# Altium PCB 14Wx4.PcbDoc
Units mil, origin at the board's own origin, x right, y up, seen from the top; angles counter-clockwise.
Board outline 11600 x 1085 mil, 2 copper layers (Top Layer, Bottom Layer); 105 components, 57 nets, 293 pads, 0 vias.
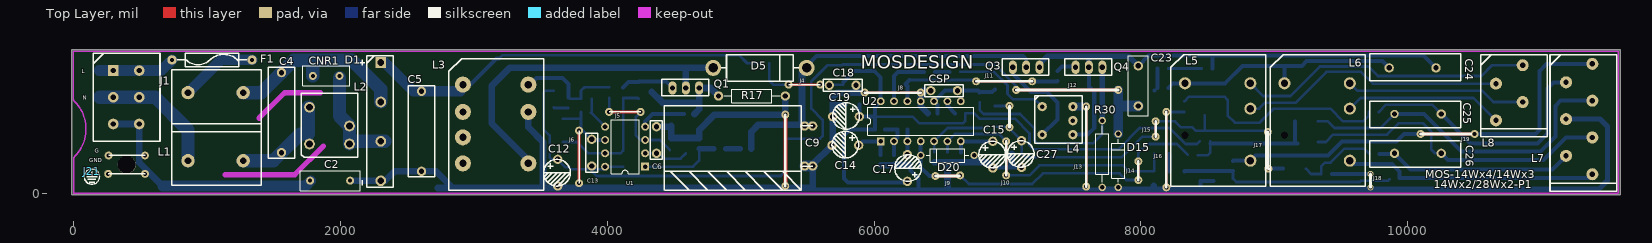
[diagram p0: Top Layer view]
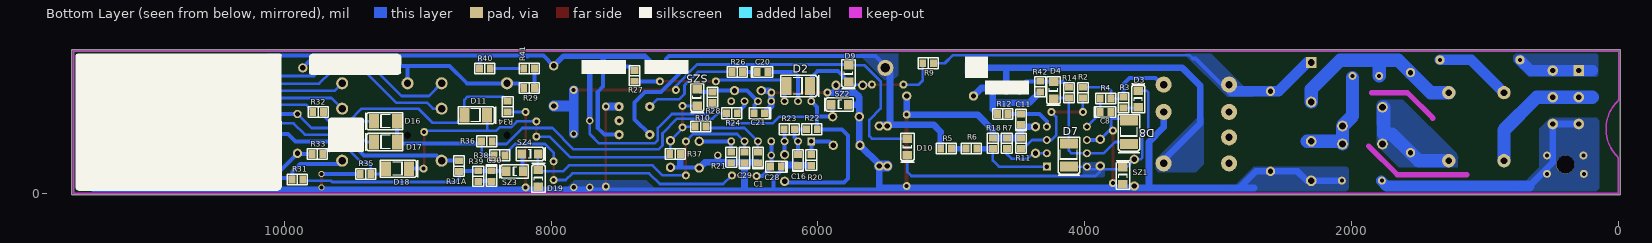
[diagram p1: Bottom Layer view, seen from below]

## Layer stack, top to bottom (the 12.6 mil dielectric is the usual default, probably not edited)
Top Layer: signal copper 1.4
Dielectric: dielectric 12.6, FR-4, Dk 4.8
Bottom Layer: signal copper 1.4

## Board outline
-10,-10 11590,-10 11590,1075 -10,1075

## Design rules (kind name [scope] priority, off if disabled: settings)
Clearance [All] p1: gap=10
HoleSize [All] p1: absolutevalues=TRUE maxlimit=150 minlimit=1 maxpercent=80.000 minpercent=20.000
PlaneClearance [All] p1: clearance=10
PolygonConnect [All] p1: connectstyle=Direct reliefconductorwidth=10 reliefentries=4 polygonreliefangle="90 Angle"
RoutingVias [All] p1: holewidth=28 width=50 viastyle="Through Hole" minholewidth=28 minwidth=50 maxholewidth=28 maxwidth=50
SolderMaskExpansion [All] p1: expansion=4
TestPointUsage [All] p1: valid=0 allowmultiple=FALSE
Testpoint [All] p1: side=15 testpointundercomponent=TRUE minsize=40 maxsize=100 preferedsize=60 minholesize=0 maxholesize=40 preferedholesize=32 testpointgrid=1 style=1023 order=0-112345678
Width [All] p1: maxlimit=100 minlimit=10 preferedwidth=10 toplayer_minwidth=20 toplayer_maxwidth=20 toplayer_prefwidth=20 bottomlayer_prefwidth=20 minimp=50.000000 maximp=50.000000 favimp=50.000000
17 further rules are at their usual default settings.

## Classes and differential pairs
component class 20081009SMD: C2 C4 C5 C6 C8 C9 C11 C12 C13 C14 C15 C16 C17 C18 C19 C20 C21 C23 C24 C25 C26 C27 C28 C29 C30 CNR1 D1 D3 D4 D5 D9 D10 D11 D15 D16 D17 D18 D19 D20 F1 J1 L1 L2 L3 L4 L5 L6 L7 Q1 Q3 Q4 R2 R3 R4 R5 R6 R7 R9 R10 R11 R12 R14 R17 R18 R20 R21 R22 R23 R24 R26 R27 R28 R29 R30 R31 R31A R32 R33 R34 R35 R36 R37 R38 R39 R40 R41 R42 SZ1 SZ2 SZ3 SZ4 U1 U2
net class NewClass: E

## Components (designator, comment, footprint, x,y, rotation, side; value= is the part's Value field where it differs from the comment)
C1 "Comment" C0805A 6450,270 r90 bottom
C2 "Cap Y1" RAD-0.3#1 1925,95 r180 top
C4 "Cap X1" RAD0.6B 1560,305 r90 top
C5 "CAP" RAD0.6B 2610,165 r90 top
C6 "CAP" RAD0.2B 4370,500 r270 top
C8 "CAP" C0805A 3845,610 r180 bottom
C9 "Cap2" RB.3/.6A 5540,505 r0 top locked
C11 "CAP" C0805A 4480,555 r90 bottom
C12 "CAP" RB.2/.2 3630,155 r0 top
C13 "Comment" RAD0.2B 3885,205 r90 top
C14 "Cap" RB.2/.2 5785,360 r270 top
C15 "Cap" RB.2/.2 6890,290 r0 top
C16 "Cap" C0805A 6150,250 r90 bottom
C17 "Cap2" RB.2/.2 6250,190 r180 top
C18 "CAP" RAD0.2B 5865,810 r180 top
C19 "Cap" RB.2/.2 5790,575 r270 top
C20 "CAP" C0805A 6415,910 r180 bottom
C21 "CAP" C0805A 6440,600 r0 bottom
C23 "CAP" RAD-0.3#2 7980,805 r270 top
C24 "CAP" RAD0.6A#1 9710,840 r0 top
C25 "CAP" RAD0.6A#2 10400,695 r180 top
C26 "CAP" RAD0.6A#1 10400,400 r180 top
C27 "Cap2" RB.2/.2 7105,295 r0 top
C28 "Cap" C0805A 6315,200 r0 bottom
C29 "Cap" C0805A 6550,270 r90 bottom
C30 "Cap" C0805A 8445,130 r270 bottom
CNR1 "CNR" RAD-0.2 1895,880 r0 top
CSP "Comment" RAD0.2B 6425,770 r0 top
D1 "DIODEx4" SIP4B 2305,980 r270 top
D2 "Comment" CD4532-1812A 6140,805 r180 bottom
D3 "DIODE" CD3216-1206A 3600,705 r90 bottom
D4 "DIODE" CD3216-1206A 4235,775 r270 bottom
D5 "HIGH EFFICIENCY DIODES" DIODE0.7A 4850,835 r0 top
D7 "Comment" CD4532-1812A 4120,280 r270 bottom
D8 "Comment" CD4532-1812A 3670,450 r270 bottom
D9 "DIODE" CD3216-1206A 5770,900 r270 bottom
D10 "DIODE" CD3216-1206A 5330,350 r270 bottom
D11 "DIODE" CD4532-1810 8555,585 r180 bottom
D15 "FFAST RECOVERY RECTIFIER" DIODE-0.4 7830,245 r90 top
D16 "Surface Mount Glass Passivated Rectifier" CD4532-1810 9250,540 r0 bottom
D17 "Surface Mount Glass Passivated Rectifier" CD4532-1810 9250,385 r0 bottom
D18 "DIODE" CD4532-1810 9140,185 r180 bottom
D19 "DIODE" CD3216-1206A 8095,110 r90 bottom
D20 "HIGH EFFICIENCY DIODES" DIODE-0.4 6550,285 r180 top
F1 "3.15A/250V" FUSE0.6 740,1000 r0 top
GND "Comment" GND 400,215 r0 top
J1 "Header 3" IDC6C 300,920 r0 top
J4 "Comment" JUMP_6mm 5360,815 r0 top
J5 "Comment" JUMP_6mm 4015,610 r0 top
J6 "Comment" JUMP_10mm 3790,470 r270 top
J21 "Comment" GND2 140,165 r0 top
L1 "INDUCTOR_EMI" EE1916H_EMI 740,60 r0 top
L2 "Inductor" Q.3/.3 1770,370 r0 top
L3 "INDUCTOR2:2_3" EE25_PFC8 3165,520 r270 top locked
L4 "INDUCTOR2:2" EE0808 7490,545 r270 top
L5 "INDUCTOR2A" EE2520_LRES8 8330,825 r0 top locked
L6 "INDUCTOR" EE2520_LRES8 9075,825 r0 top
L7 "Comment" IDC14-MIN 11065,1040 r270 top
L8 "Comment" IDC8-MIN 10660,960 r270 top
Q1 "MOSFET-N" TO-220D 4590,790 r0 top
Q3 "MOSFET-N" TO-220D 7140,945 r0 top
Q4 "MOSFET-N" TO-220D 7610,945 r0 top
R2 "RES1" 2012[0805]A 4015,755 r270 bottom
R3 "RES1" 2012[0805]A 3710,680 r270 bottom
R4 "RES1" 2012[0805]A 3845,710 r0 bottom
R5 "RES1" 2012[0805]A 5040,335 r0 bottom
R6 "RES1" 2012[0805]A 4850,335 r180 bottom
R7 "Res1" 2012[0805]A 4585,375 r270 bottom
R9 "RES1" 2012[0805]A 5175,975 r180 bottom
R10 "RES1" 2012[0805]A 6880,500 r180 bottom
R11 "RES1" 2012[0805]A 4480,375 r90 bottom
R12 "RES1" 2012[0805]A 4615,595 r0 bottom
R14 "RES1" 2012[0805]A 4120,755 r90 bottom
R17 "RES1" AXIAL-0.5#1 5085,730 r180 top
R18 "RES1" 2012[0805]A 4690,375 r270 bottom
R20 "RES1" 2012[0805]A 6050,250 r90 bottom
R21 "RES1" 2012[0805]A 6650,270 r90 bottom
R22 "RES1" 2012[0805]A 6045,480 r180 bottom
R23 "RES1" 2012[0805]A 6215,480 r0 bottom
R24 "RES1" 2012[0805]A 6645,600 r0 bottom
R26 "RES1" 2012[0805]A 6605,910 r180 bottom
R27 "RES1" 2012[0805]A 7375,880 r90 bottom
R28 "RES1" 2012[0805]A 6790,720 r90 bottom
R29 "Res1" 2012[0805]A 8165,790 r180 bottom
R30 "RES1" AXIAL-0.5#2 7710,295 r90 top
R31 "RES1" 2012[0805]A 9900,105 r0 bottom
R31A "RES1" 2012[0805]A 8690,205 r90 bottom (schematic designator R31)
R32 "RES1" 2012[0805]A 9745,610 r180 bottom
R33 "RES1" 2012[0805]A 9750,295 r180 bottom
R34 "RES1" 2012[0805]A 8325,650 r90 bottom
R35 "RES1" 2012[0805]A 9390,145 r180 bottom
R36 "RES1" 2012[0805]A 8480,390 r180 bottom
R37 "RES1" 2012[0805]A 7070,295 r0 bottom
R38 "RES1" 2012[0805]A 8385,285 r180 bottom
R39 "RES1" 2012[0805]A 8545,130 r90 bottom
R40 "Res1" 2012[0805]A 8495,935 r180 bottom
R41 "Res1" 2012[0805]A 8165,935 r0 bottom
R42 "RES1" 2012[0805]A 4335,800 r270 bottom
SZ1 "Zener" CD3216-1206A 3715,130 r90 bottom
SZ2 "Zener" CD3216-1206A 5835,665 r0 bottom
SZ3 "Zener" CD3216-1206A 8270,165 r0 bottom
SZ4 "Zener" CD3216-1206A 8160,295 r180 bottom
SZ5 "Comment" CD3216-1206A 6905,720 r270 bottom
U1 "IC" DIP-8 4135,350 r90 top
U2 "IC" DIP-14 6350,540 r0 top

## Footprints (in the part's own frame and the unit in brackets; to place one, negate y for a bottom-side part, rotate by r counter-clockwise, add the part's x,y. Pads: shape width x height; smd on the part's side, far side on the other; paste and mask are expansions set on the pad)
2012[0805]A [mm] "Chip Resistor; Body 2.0 x 1.3 mm (LxW typ)"
  rect 1.3x1.5 smd: 1(-1.016,0) 2(1.016,0)
  silkscreen extent -1.91,-1.02 1.91,1.02
AXIAL-0.5#1 [mil] "Semiconductor Resistor; 2 Leads"
  round 70 hole 40: 1(-250,0) 2(250,0)
  silkscreen extent -210,-50 210,50
AXIAL-0.5#2 [mil] "Semiconductor Resistor; 2 Leads"
  round 55.12 hole 33.46: 1(-250,0) 2(250,0)
  silkscreen extent -210,-50 210,50
C0805A [mm] "Chip Capacitor; Body 2.0 x 1.2 mm (LxW typ)"
  rect 1.3x1.5 smd: 1(-1.016,0) 2(1.016,0)
  silkscreen extent -2.16,-1.02 1.91,1.02
CD3216-1206A [mm] "Chip Diode; Body 3.2 x 1.6 mm (LxW typ)"
  rect 1.6x1.8 smd: 1(-1.524,0) 2(1.651,0)
  silkscreen extent -2.54,-1.27 2.92,1.27
CD4532-1810 [mm] "Chip Diode; Body 4.5 x 3.2 mm (LxW typ)"
  rect 1.9x2.8 smd: 1(-2.413,0) 2(1.95,0)
  silkscreen extent -3.56,-1.65 3.56,1.65
CD4532-1812A [mm] "Chip Diode; Body 4.5 x 3.2 mm (LxW typ)"
  rect 1.9x3.4 smd: 1(-2.413,0) 2(2.032,0)
  silkscreen extent -3.56,-2.03 3.68,2.03
DIODE0.7A [mil]
  round 120 hole 70: 1(-55,105) 2(645,105)
  silkscreen extent 5,5 585,205
DIODE-0.4 [mm] "Tunnel Diode - Dependent Source Model; 2 Leads"
  round 1.4 hole 0.85: 1(-5.08,0) 2(5.08,0)
  silkscreen extent -4.06,-1.27 4.06,1.27
DIP-8 [mm] "DIP; 8 Leads; Row Spacing 7.62 mm; Pitch 2.54 mm"
  rect 1.5x1.5 hole 0.9: 1(-3.81,-3.81)
  round 1.5 hole 0.9: 2(-1.27,-3.81) 3(1.27,-3.81) 4(3.81,-3.81) 5(3.81,3.81) 6(1.27,3.81) 7(-1.27,3.81) 8(-3.81,3.81)
  silkscreen extent -5.15,-2.65 5.15,2.65
DIP-14 [mm] "DIP; 14 Leads; Row Spacing 7.62 mm; Pitch 2.54 mm"
  rect 1.5x1.5 hole 0.9: 1(-7.62,-3.81)
  round 1.5 hole 0.9: 2(-5.08,-3.81) 3(-2.54,-3.81) 4(0,-3.81) 5(2.54,-3.81) 6(5.08,-3.81) 7(7.62,-3.81) 8(7.62,3.81) 9(5.08,3.81) 10(2.54,3.81) 11(0,3.81) 12(-2.54,3.81) 13(-5.08,3.81) 14(-7.62,3.81)
  silkscreen extent -10.1,-2.65 10.1,2.65
EE25_PFC8 [mil]
  round 120 hole 55: 1(-295,-245) 2(-90,-245) 3(100,-245) 4(295,-245) 5(295,245) 7(-90,245) 8(-295,245)
  silkscreen extent -490,-350 495,360
EE0808 [mil]
  round 70 hole 35: 1(-105,-230) 3(105,-230) 4(105,0) 5(0,0)
  round 70 hole 32: 6(-105,0)
  silkscreen extent -185,-285 170,70
EE1916H_EMI [mil]
  round 100 hole 50: 1(120,185) 2(533.5,185) 3(533.5,695) 4(120,695)
  silkscreen extent 0,0 669,866
EE2520_LRES8 [mil]
  round 0 hole 55: 0(0,-390)
  round 90.55 hole 55: 1(0,0) 5(490,-580) 7(490,-190) 8(490,0)
  silkscreen extent -105,-770 605,215
FUSE0.6 [mil]
  round 70 hole 32: 1(0,0) 2(600,0)
  silkscreen extent 40,-50 560,50
GND [mil] "GND"
  round 60 hole 30: ""(-137.8,-68.9) ""(-135,68.9) ""(137.8,-68.9) ""(137.8,68.9)
  round 135 hole 135: ""(0,0)
  silkscreen extent -138,-69 138,69
GND2 [mil]
  silkscreen extent -57,-97 57,17
IDC6C [mil]
  rect 80x80 hole 40: 1(0,0)
  round 80 hole 40: 1(195,0) 2(0,-200) 2(195,-200) 3(0,-400) 3(195,-400)
  silkscreen extent -150,-530 350,130
IDC8-MIN [mil]
  round 90 hole 40: 1(0,200) 2(137.8,0) 3(275.59,200) 4(413.39,0)
  silkscreen extent -80,-115 535,385
IDC14-MIN [mil]
  round 90 hole 40: 1(70,316.85) 2(207.8,120) 3(345.59,316.85) 4(483.39,120) 5(621.18,316.85) 6(758.98,120) 7(896.77,316.85)
  silkscreen extent 0,0 1024,500
JUMP_6mm [mil]
  round 60 hole 30: 1(0,0) 2(236.22,0)
  silkscreen extent 0,0 236,0
JUMP_10mm [mil]
  round 60 hole 30: 1(0,0) 2(393.7,0)
  silkscreen extent 0,0 394,0
Q.3/.3 [mil]
  round 80 hole 50: 1(0,0) 1(0,275) 2(300,0) 2(300,135)
  silkscreen extent -60,-100 360,380
RAD0.2B [mil]
  round 70 hole 40: 1(0,0) 2(200,0)
  silkscreen extent -45,-45 245,45
RAD0.6A#1 [mil]
  round 70 hole 40: 1(150,100) 2(500,100)
  silkscreen extent 5,5 685,205
RAD0.6A#2 [mil]
  round 70 hole 40: 1(150,100)
  round 62.99 hole 40: 2(500,100)
  silkscreen extent 5,5 685,205
RAD0.6B [mil]
  round 70 hole 40: 1(0,0) 2(600,0)
  silkscreen extent -40,-100 640,100
RAD-0.2 [mil] "Jumper Wire; 2 Leads"
  round 60 hole 30: 1(-100,0) 2(100,0)
  silkscreen extent -175,-75 175,75
RAD-0.3#1 [mil] "Capacitor; 2 Leads"
  round 60 hole 30: 1(-150,0) 2(150,0)
  silkscreen extent -225,-75 225,75
RAD-0.3#2 [mil] "Capacitor; 2 Leads"
  round 70 hole 40: 1(-150,0) 2(150,0)
  silkscreen extent -225,-75 225,75
RB.2/.2 [mil]
  round 70 hole 40: 1(0,100) 2(0,-100)
  silkscreen extent -105,-100 95,100
RB.3/.6A [mil]
  round 70 hole 40: 1(0,0) 2(0,-300)
  silkscreen extent -1110,-480 0,150
SIP4B [mil]
  rect 80x80 hole 50: 1(0,0)
  round 80 hole 50: 2(295.28,0) 3(590.55,0) 4(885.83,0)
  silkscreen extent -50,-160 935,92
TO-220D [mil]
  oval 60x100 hole 40: 1(0,0) 2(-100,0) 3(100,0)
  silkscreen extent -180,-60 170,65

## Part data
C2: library part CAP, "Y Capacitor"
C4: library part CAP, "BOX Capacitor"
C5 C23 C24 C25 C26: "POLYPROPYLENE FILM Capacitor"
C6 C8 C11 C16 C18 C20 C21 C28 C29 C30: "Ceramic Capacitor"
C9 C17 C27: "Electrolytic Capacitor"
C12 C14 C15 C19: library part Cap2, "Electrolytic Capacitor"
CNR1: "Varistor"
D3 D4 D9 D10 D11 D18 D19: "Diode  75V,1A"
D5: library part DIODE, "Diode HIGH EFFICIENCY RECTIFIERS 600V, 3A"
D15 D16 D17: library part DIODE, "Diode FAST RECOVERY RECTIFIER 700V,1A"
D20: library part DIODE, "Diode HIGH EFFICIENCY RECTIFIERS 600V, 1A"
F1: library part FUSE2, "Fuse"
J1: "Jumper Wire Pin spacing 5mm         235-403(2LG+1G)"
L1: "EE19 Inductor"
L2: "DR1012 Inductor"
L3 L5: "EE25 Inductor"
L4: "EE08 Inductor"
L6: library part INDUCTOR2A, "EE25 Inductor"
Q1: "Transistor, MOSFET  600V, 11A"
Q3 Q4: "Transistor, MOSFET  600V, 6A"
R2 R3 R4 R5 R6 R9 R10 R11 R12 R14 R18 R20 R21 R22 R23 R24 R26 R27 R28 R29 R31 R31A R32 R33 R34 R35 R36 R37 R38 R39 R40 R41 R42: "Resistor 1/4W"
R7: "Resistor"
R17 R30: "Resistor 1W"
SZ1 SZ2: library part "D Zener", "Zener Diode 1W"
SZ3 SZ4: library part "D Zener", "Zener Diode 1/4W"
U1: library part 59039, "IC, Power Factor Controller"
U2: library part M8145, "IC, Ballast Driver"

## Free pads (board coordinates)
  round 60 hole 30: 0(5335,590) 0(6645,135) 0(7015,655) 0(7065,775) 0(7185,840) 0(7980,100) 1(5335,55) 1(6765,840) 1(6990,390) 1(7015,495) 1(7980,240) 2(6990,135) 3(7590,650) 4(7590,50) 5(6350,755) 5(7830,775) 6(5930,755) 7(6460,130) 8(8955,185) 8(10095,445) 9(8950,460) 9(10500,445) 17(8110,540) 18(8110,425) 19(8190,45) 20(8190,610)
  round 70 hole 40: 0(5480,505) 2(5480,205)
  round 45 hole 30: 11(9720,145) 12(9720,45)

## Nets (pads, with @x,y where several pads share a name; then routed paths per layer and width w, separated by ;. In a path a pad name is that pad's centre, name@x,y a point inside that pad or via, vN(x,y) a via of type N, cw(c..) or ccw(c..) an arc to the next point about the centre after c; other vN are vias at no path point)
E: C1.1 C2.1 C5.1 C6.1 C8.2 C9.2 C11.1 C12.2 C13.2 C14.2 C15.2 C16.1 C18.1 C19.2 C21.1 C27.2 C28.1 C29.1 C30.2 CSP.1 D1.4 D8.1 D15.1 D19.1 D20.1 J6.1 J6.2 L3.7 L4.6 L7.4 pad.0@5335,590 pad.1@5335,55 pad.2@5480,205 pad.3 pad.4 pad.5@6350,755 pad.6 pad.11 pad.12 pad.19 pad.20 R7.1 R11.2 R17.1 R18.1 R20.1 R21.1 R30.1 R34.1 R35.1 R37.1 R39.1 SZ1.1 SZ2.1 U1.6 U2.11 | length 19133.5
  Top Layer w20: J6.2 J6.1 ; pad.6 pad.5@6350,755 ; pad.4 pad.3 ; pad.19 pad.20 ; pad.12 pad.11
  Top Layer w30: pad.1@5335,55 pad.0@5335,590
  Bottom Layer w20: D8.1@3670,560 3805,560 ; 3790,40 J6.2 ; J6.1 J6.1@3800,480 ; C8.2 3805,560 ; C13.2 3810,480 J6.1@3800,480 ; C11.1@4475,500 4480,505 C11.1 C11.1@4480,520 ; pad.20 R34.1 ; 8455,25 8455,30 ; J6.1@3800,480 3805,485 3805,560
  Bottom Layer w30: C13.2 3890,400 U1.6 ; 5525,55 5540,40 5550,30 6335,30 ; C28.1@6262.4,212.6 C28.1 6275,170 6335,110 6335,30 ; U2.11@6347.6,692.4 U2.11 ; pad.5@6350,755 pad.5@6365,770 ; C29.1 C29.1@6550,232.6 ; C15.2 C15.2@6897.6,197.6 ; C15.2@6897.6,195 C27.2 ; 7032.6,207.4 7035,205 ; R30.1@7710,30 6335,30 ; 8455,30 8445,30 C30.2 8445,92.6 R39.1@8545,92.6 ; R35.1 9550,145 ; 9500,145 9550,145 ; pad.11 9550,145
  Bottom Layer w40: R30.1@7710,30 11430,30 11495,95 11495,500 11438.39,556.61 L7.4
  Bottom Layer w50: C2.1 2335.83,95 2405.83,165 C5.1 2720,165 2840,45 ; 2730,40 3790,40 5540,40 C9.2 5540,215 C14.2 ; L3.7 3410,495 3520,385 3520,50 ; C6.1 C11.1@4475,500 ; C11.1@4480,505 R11.2 R7.1 R18.1 4690,475 4805,590 5335,590 R17.1 ; C14.2@5690,360 C19.2 5690,666 ; SZ2.1 5691,665 5690,666 ; C18.1 5865,755 ; pad.6 5865,755 ; R20.1 6147.4,210 6150,212.6 C28.1@6262.4,212.6 ; pad.5@6350,755 U2.11 6350,652.6 C21.1@6402.6,600 ; pad.5@6365,770 CSP.1 ; C1.1@6450,232.6 6550,232.6 6750,232.6 ; 6550,45 C29.1 ; D20.1 6750,232.6 ; C15.2 6847.4,232.6 6750,232.6 ; 7032.6,207.4 R37.1@7032.6,295 ; D19.1@8095,54.88 8095,45 D19.1@8100,40 ; 5690,666 5690,721 5724,755 5865,755
  Bottom Layer w60: L4.6 pad.3
  Bottom Layer w80: pad.2@5480,205 C9.2
L: F1.1 J1.1 | length 578.1
  Bottom Layer w80: 195,920 495,920 660,920 F1.1
N: J1.2 L1.1 | length 1101.5
  Bottom Layer w100: 200,720 300,720 495,720 615,720 860,475 L1.1 860,355
NetC2_2: C2.2 GND. J1.3 | length 1859.1
  Bottom Layer w50: J1.3@300,520 495,520 495,230 670,55
  Bottom Layer w80: 670,55 1740,55 C2.2@1780,95
NetC4_1: C4.1 L1.2 L2.1 | length 769.3
  Bottom Layer w100: L1.2 1500,245 C4.1 1700,445 1760,445 L2.1@1760,645
NetC5_2: C5.2 D1.1 L3.1 R9.2 | length 2930
  Bottom Layer w20: 3190,1010 3215,1035 4990,1035 5050,975 R9.2
  Bottom Layer w30: L3.1@2975,815 3170,1010 3190,1010
  Bottom Layer w80: D1.1@2335,980 2550,765 L3.1@2900,765
NetC6_2: 
NetC8_1: C8.1 R4.2 | length 100
  Bottom Layer w20: C8.1 R4.2
NetC9_1: C9.1 D5.2 pad.0@5480,505 Q3.1 R5.2 | length 2843.2
  Bottom Layer w30: D5.2 5520,965 5520,980 5570,1030 7115,1030 7140,1005 Q3.1@7140,950
  Bottom Layer w50: R5.2 5080,460 5135,515 pad.0@5460,515 ; D5.2@5520,965 5460,905 pad.0@5460,515 ; C9.1 5530,515 pad.0@5460,515
NetC11_2: C11.2 R12.1 U1.4 | length 352.8
  Bottom Layer w30: U1.4 4285,540 4340,595 C11.2 R12.1
NetC12_1: C12.1 C13.1 D3.2 D7.2 D10.2 SZ1.2 U1.8 | length 2744.1
  Bottom Layer w20: D3.2 3540,770 3525,755 3525,480 3570,435 3570,270 3585,255 C12.1 SZ1.2@3690,195 ; SZ1.2@3730,180 C13.1@3890,180 ; D7.2 U1.8 3965,180 C13.1@3890,180 ; D10.2 5330,160 5300,130 3920,130 3890,160 C13.1@3890,180
NetC14_1: C14.1 R20.2 U2.1 | length 280
  Bottom Layer w30: C14.1 5915,390 U2.1 R20.2@6050,287.4
NetC15_1: C15.1 R21.2 U2.7 | length 322.6
  Bottom Layer w30: R21.2@6650,307.4 U2.7 C15.1
NetC16_2: C16.2 R22.1 R23.1 U2.2 | length 299.2
  Bottom Layer w30: R22.1@6082.4,480 6177.6,480 6177.6,417.6 U2.2 C16.2@6150,287.4
NetC17_2: C17.2 R23.2 U2.3 | length 191
  Bottom Layer w30: C17.2 U2.3 6250,477.6 R23.2@6252.4,480
NetC20_1: C20.1 R26.2 | length 110
  Bottom Layer w30: C20.1 R26.2
NetC20_2: C20.2 U2.13 | length 427.4
  Bottom Layer w30: U2.13 6150,880 6180,910 C20.2
NetC21_2: C21.2 CSP.2 R28.2 SZ5.1 U2.10 | length 603
  Bottom Layer w30: C21.2@6477.4,600 6477.4,662.6 U2.10 6530,770 CSP.2 6777.4,770 R28.2@6790,757.4 ; R28.2 6885,760 SZ5.1
NetC23_1: C23.1 C24.2 L4.4 Q3.3 Q4.1 R40.1 | length 4072.6
  Bottom Layer w30: L4.4 7600,440 7650,490 7650,760 7610,800 Q4.1@7610,940 ; C23.1 8057.24,1032.24 8185,1032.24 ; 8147.24,1032.24 8185,1032.24 ; 8177.4,1024.65 8185,1032.24 ; R40.1 8535,1025 ; C24.2 10117.76,1032.24 8270,1032.24 ; 8185,1032.24 8270,1032.24 ; 8185,1032.24 8270,1032.24
  Bottom Layer w40: Q3.3@7240,950 7240,968.99 7299,1027.99 7610,1027.99 ; Q4.1@7610,940 7610,1027.99 ; C23.1 7907.01,1027.99 7610,1027.99
NetC23_2: C23.2 D9.1 D10.1 D15.2 pad.0@7065,775 pad.5@7830,775 | length 3649.5
  Top Layer w20: pad.0@7065,775 pad.5@7830,775
  Bottom Layer w20: D10.1 5595,410 5615,430 5615,550 5530,635 5530,840 5650,960 D9.1@5759.88,960 ; D9.1@5764.88,965 6905,965 7065,805 pad.0@7065,775
  Bottom Layer w70: D15.2 pad.5@7830,775
  Bottom Layer w80: 7840,655 C23.2
NetC25_1: C25.2 D16.2 L7.3 | length 2527.1
  Bottom Layer w20: D16.2 9400,540 9450,490 9795,490 C25.2
  Bottom Layer w30: C25.2 10120,595 10400,315 10995,315 11105,425 11105,655 11144.41,694.41 L7.3
NetC25_2: C25.1 L7.2 R32.1 | length 1931.1
  Bottom Layer w20: R32.1@9782.4,610 9837.4,665 10180,665 C25.1
  Bottom Layer w30: C25.1 10470,375 10970,375 11045,450 11045,785 11092.2,832.2 L7.2
NetC26_1: C26.1 D17.2 L7.5 | length 2390.1
  Bottom Layer w20: D17.2 9385,385 9440,440 9845,440 9930,525 10115,525 10175,465 10175,330 10205,300 C26.1
  Bottom Layer w30: C26.1@10245,300 C26.1@10255,290 ; C26.1 10300,250 11016.18,250 11185,418.82 L7.5
NetC26_2: C26.2 L7.6 R33.1 | length 1491.2
  Bottom Layer w30: R33.1@9787.4,295 9895,295 C26.2 10020,180 11083.98,180 L7.6
NetC27_1: C27.1 D11.2 D18.2 pad.0@7015,655 pad.1@7015,495 pad.8@8955,185 pad.9@8950,460 pad.17 pad.18 R10.1 R37.2 SZ5.2 | length 3182.1
  Top Layer w20: pad.1@7015,495 pad.0@7015,655 ; pad.18 pad.17 ; pad.9@8950,460 8950,190 pad.8@8955,185
  Bottom Layer w20: SZ5.2 pad.0@7015,655 ; R10.1@6917.4,500 7000,500 C27.1 ; C27.1@7105,387.4 C27.1 ; R37.2@7107.4,295 7107.4,392.6 C27.1 ; R37.2@7107.4,300 7137.4,270 7855,270 8010,425 pad.18 ; C27.1@7107.4,397.4 C27.1 ; pad.17 8255,540 8300,495 8385,495 8410,470 8475,470 ; D11.2 8478.23,473.23 8475,470 ; pad.9@8950,460 8940,470 8475,470
  Bottom Layer w30: pad.8@8955,185 D18.2
NetC28_1: C28.2 D20.2 pad.0@6645,135 pad.0@7980,100 pad.1@7980,240 pad.7 R38.2 U2.4 | length 2562.8
  Top Layer w20: pad.7 pad.0@6640,130 ; pad.0@7980,100 pad.1@7980,240
  Bottom Layer w20: pad.0@6645,135 6710,70 7185,70 7265,150 7840,150 7890,100 pad.0@7980,100 ; pad.1@7980,240 7980,305 8045,370 8270,370 R38.2@8350,290
  Bottom Layer w30: U2.4 6350,195 6415,130 pad.7
NetC30_1: C30.1 R31.1 R31A.1 R39.2 SZ3.2 | length 1614.8
  Bottom Layer w20: R31A.1@8690,167.6 8690,110 8715,85 9640,85 9650,95 9852.6,95 R31.1@9862.6,105
  Bottom Layer w30: SZ3.2@8325.12,165 8327.72,167.6 R31A.1@8690,167.6
NetCNR1_1: C4.2 CNR1.1 D1.2 L1.3 | length 1433.5
  Bottom Layer w100: L1.3 1410,755 C4.2 1652.5,997.5 1787.5,997.5 1795,990 ; CNR1.1 1795,990 ; D1.2 2305,780 2087.5,997.5 1802.5,997.5 1795,990
NetCNR1_2: CNR1.2 D1.3 L2.2 | length 791.1
  Bottom Layer w100: CNR1.2@1995,865 1995,580 2070,505 L2.2@2070,389.45 ; L2.2@2070,370 L2.2@2070,389.45 ; D1.3@2335,389.45 L2.2@2070,389.45
NetD3_1: D3.1 R3.2 | length 112.1
  Bottom Layer w20: D3.1 3605,640 R3.2
NetD4_1: D4.1 Q1.2 R14.2 R42.1 | length 409.4
  Bottom Layer w30: R14.2 4160,835 D4.1 4240,840 R42.1 4440,840 Q1.2
NetD4_2: D4.2 D7.1 D8.2 R14.1 U1.7 | length 1005.6
  Bottom Layer w20: D8.2@3670,385 3775,385 3860,300 4100,300 4120,320 D7.1 R14.1 4230,715 D4.2
NetD5_1: D5.1 L3.5 Q1.1 | length 2570.2
  Bottom Layer w50: L3.5@3435,225 3135,525 3135,805 3270,940 4590,940 ; Q1.1 4590,940 ; D5.1 4590,940
NetD11_1: D11.1 R32.2 R34.2 | length 1673.1
  Bottom Layer w20: R34.2 8360,725 8625,725 8650,700 D11.1 8705,530 8890,530 8995,635 9420,635 9515,540 9665,540 9707.6,582.6 R32.2@9707.6,610
NetD16_1: D16.1 D17.1 R36.1 R38.1 | length 996.5
  Bottom Layer w20: R38.1 8500,285 8520,305 R36.1
  Bottom Layer w30: R36.1@8520,375 D17.1@9173.23,375 ; D17.1 D16.1
NetD18_1: D18.1 R33.2 R35.2 | length 621.7
  Bottom Layer w20: D18.1 9275,145 R35.2 9350,200 9380,230 9420,230 9525,335 9672.6,335 R33.2@9712.6,295
NetF1_2: F1.2 L1.4 | length 581.5
  Bottom Layer w80: L1.4 1105,1000 F1.2
NetL3_8: L3.8 R2.1 R3.1 R4.1 | length 918
  Bottom Layer w20: L3.8 L3.8@3420,815 ; R2.1 3830,795 3805,770 R4.1 ; R3.1@3720,710 R4.1 ; R3.1@3720,710 R3.1 R3.1@3720,710 ; R3.1@3720,710 R4.1
  Bottom Layer w30: L3.8@3420,815 3470,865 3665,865 3710,820 R3.1
NetL4_1: L4.1 R26.1 | length 760.8
  Bottom Layer w20: R26.1 6900,910 7000,810 7000,745 7040,705 7205,705 L4.1
NetL4_3: L4.3 Q3.2 | length 766.7
  Bottom Layer w30: Q3.2@7040,950 7040,895 7175,760 7295,760 7375,680 7375,555 L4.3
NetL5_5: L5.5 L7.1 pad.8@10095,445 pad.9@10500,445 R31A.2 | length 3228.6
  Top Layer w20: pad.8@10095,445 pad.9@10470,445
  Bottom Layer w30: R31A.2@8690,242.4 8692.6,245 L5.5 ; L5.5@8812.4,245 L5.5 ; pad.8@10095,445 9970,445 9915,390 9505,390 9400,285 8860,285 L5.5 ; pad.9@10500,445 10955,445 10985,475 10985,915 11040,970 L7.1
NetL6_5: L6.5 L7.7 R31.2 | length 1910.3
  Bottom Layer w30: L6.5 9590,220 9880,220 9937.4,162.6 9937.4,115 11353.62,115 L7.7
NetQ1_3: Q1.3 R12.2 R17.2 R42.2 | length 757.5
  Bottom Layer w50: R42.2 4415,680 4680,680 ; R12.2 4690,630 Q1.3 4775,790 R17.2
NetQ4_2: Q4.2 R27.2 | length 148.5
  Bottom Layer w30: R27.2@7375,917.4 7407.6,950 Q4.2@7510,950
NetQ4_3: Q4.3 R28.1 R30.2 | length 1796.9
  Bottom Layer w20: R28.1@6792.4,682.6 6792.4,622.6 6820,595 7095,595 7200,490 7200,400 7225,375 7640,375 7710,445 7710,675
  Bottom Layer w40: R30.2 Q4.3@7710,950
NetR2_2: R2.2
NetR5_1: R5.1 R6.1 | length 110
  Bottom Layer w40: R6.1 R5.1
NetR6_1: R6.2 R18.2 U1.1 | length 623.6
  Bottom Layer w20: U1.1 4645,200 4690,245 R18.2
  Bottom Layer w40: R18.2 R6.2@4800,335
NetR10_2: C1.2 R10.2 U2.5 | length 516.6
  Bottom Layer w20: C1.2@6450,307.4 U2.5 6550,490 R10.2@6842.6,490
NetR24_1: R24.1 U2.9 | length 117.3
  Bottom Layer w30: U2.9@6552.4,687.6 U2.9 6550,657.6 R24.1@6607.6,600
NetR27_1: D2.1 pad.0@7185,840 pad.1@6765,840 R27.1 U2.12 | length 1279.7
  Top Layer w20: pad.1@6765,840 pad.0@7185,840
  Bottom Layer w20: D2.1@6265,850 pad.1@6755,850
  Bottom Layer w30: D2.1@6235,820 D2.1@6265,850 ; D2.1@6245,810 6250,805 U2.12 ; pad.1@6755,850 pad.1@6765,840 ; pad.0@7185,840 7372.4,840 R27.1@7375,842.6
NetR29_2: R29.2 R41.1 | length 148.7
  Bottom Layer w30: R29.2@8100,772.6 R29.2@8102.6,770 ; R29.2 R41.1
NetR40_2: R40.2 R41.2 | length 250
  Bottom Layer w20: R41.2 R40.2
NetSZ3_1: SZ3.1 SZ4.1 | length 132
  Bottom Layer w30: SZ4.1@8210.12,295 8214.88,290.24 SZ3.1@8214.88,165
SD3A: C24.1 L5.1 L6.1 R29.1 | length 1902.2
  Bottom Layer w30: R29.1 8240,825 L5.1 8630,825 8760,955 9075,955 ; L6.1@9072.4,837.6 L6.1@9075,835 ; C24.1 9810,990 9240,990 9205,955 9075,955 ; L6.1@9075,835 L6.1 L6.1@9075,835 ; L6.1@9075,835 9075,955
SD3B: C29.2 D19.2 pad.1@6990,390 pad.2@6990,135 SZ4.2 U2.6 | length 2112.7
  Top Layer w20: pad.2@6990,135 pad.1@6990,390
  Bottom Layer w20: C29.2@6550,307.4 U2.6 6605,445 6935,445 pad.1@6990,390 ; pad.2@6990,135 7165,135 7240,210 7865,210 7910,165 8099.88,165 SZ4.2@8099.88,295
VCC: C17.1 C18.2 C19.1 D2.2 D9.2 J4.1 J4.2 R9.1 R22.2 R24.2 R36.2 SZ2.2 U2.14 | length 5541.6
  Top Layer w20: J4.1@5355,815 J4.2@5591.22,815
  Bottom Layer w20: R9.1 5215,845 5245,815 J4.1 ; J4.2 D9.2@5770,815 ; 5997.72,575.12 6007.6,575.12 6289.88,575.12 6340,525 6665,525 6682.4,542.4 6682.4,600 R24.2 6750,600 6764.07,585.93 ; 6755,595 6764.07,585.93 ; R36.2 8420,370 8335,370 8215,490 7990,490 7830,330 7195,330 7165,360 7165,450 7055,560 6790,560 6764.07,585.93
  Bottom Layer w30: D9.2 5850,915 6005,915 6050,870 U2.14 6007.6,647.6 6007.6,585 ; C19.1 C19.1@5890.12,575.12 ; SZ2.2@5890.12,665 C19.1@5890.12,575.12 ; C17.1@6250,80 5805,80 5775,110 5775,435 5820,480 R22.2 6007.6,480 6007.6,575.12 6007.6,585 ; C19.1@5890.12,575.12 5997.72,575.12 6007.6,585
pads on no net: C6.2 J5.1 J5.2 L3.2 L3.3 L3.4 L4.5 L5.0 L5.7 L5.8 L6.0 L6.7 L6.8 L8.1 L8.2 L8.3 L8.4 R7.2 R11.1 U1.2 U1.3 U1.5 U2.8
copper on no net: | length 8137.7
  Top Layer w20: 4013.78,610 4250,610
  Bottom Layer w20: 3690,195 3715,195 3730,180 ; 3880,605 3985,500 ; 4015,610 4015,715 ; 4251.22,610 4215,573.78 4215,435 4250,400 4285,400 4395,400 4470,325 ; 4285,300 4390,300 4430,260 4550,260 4589.38,299.38 ; 8820,635 8885,635 8930,680 9160,680 9390,910 9650,910 9737.8,822.2 10660,822.2 ; 8820,825 8915,730 9120,730 9195,805 9340,950 9705,950 9775,880 10550,880 10630,960 10860,960 ; 9565,635 9645,715 9690,715 10491.61,715 10660,546.61 ; 9565,825 9620,770 10555,770 10640.59,684.41 10668.82,684.41 10860,684.41

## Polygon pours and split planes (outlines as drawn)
NetD5_1 on Bottom Layer "Bottom Layer-No Net" (solid, pour order 1002): 4775,990 4890,990 4900,980 4900,895 4885,880 4790,880 4770,900 4770,985 4775,990
NetC5_2 on Bottom Layer "Bottom Layer-No Net" (solid, pour order 1008): 3205,1045 3055,1045 2735,725 2935,725 3255,1045 3205,1045
E on Bottom Layer "Bottom Layer-No Net" (solid, pour order 1004): 7230,45 7285,100 7825,100 7895,30 7895,15 7230,15 7230,45
L on Bottom Layer "Bottom Layer-No Net" (solid, pour order 1002): 300,875 675,875 790,990 790,1030 770,1050 170,1050 155,1035 155,885 165,875 300,875
NetC2_2 on Bottom Layer "Bottom Layer-No Net" (solid, pour order 1000): 300,565 515,565 545,535 595,485 595,195 775,15 780,15 170,15 145,40 145,545 165,565 300,565
NetC4_1 on Bottom Layer "Bottom Layer-No Net" (solid, pour order 1000): 1270,195 1650,195 1815,360 1815,665 ccw(c1780,665) 1780,700 1620,700 1220,300 ccw(c1256.21,263.79) 1205,263.79 1205,195 1270,195
E on Bottom Layer "Bottom Layer-No Net" (solid, pour order 1001): 2860,15 2055,15 cw(c2055,45) 2025,45 2025,180 cw(c2045,180) 2045,200 2735,200 2920,15 2860,15
NetD5_1 on Bottom Layer "Bottom Layer-No Net" (solid, pour order 1002): 3410,160 3170,160 3130,200 3110,220 3110,575 3150,575 3465,260 3470,255 3470,190 3470,180 3450,160 3410,160
NetC9_1 on Bottom Layer "Top Overlay-No Net" (solid, pour order 1000): 5535,880.79 5690,1039.87 5685,1045 5400,1045 5400,885.92 5435,850 5500,850 5505,850 5550,896.18
NetC12_1 on Bottom Layer "Bottom Layer-No Net" (solid, pour order 1003): 3982.5,235 3862.5,235 3852.5,225 3852.5,130 3862.5,120 4007.5,120 4017.5,130 4017.5,225 4007.5,235 3982.5,235
no net on Bottom Overlay "Bottom Layer-No Net" (solid): 10050,20.82 11540,20.82 ccw(c11540,40.82) 11560,40.82 11560,1030.82 ccw(c11545,1030.82) 11545,1045.82 10030,1045.82 ccw(c10030,1035.82) 10020,1035.82 10020,50.82 ccw(c10050,50.82) 10050,20.82
no net on Bottom Overlay "Bottom Layer-No Net" (solid): 9405,565 9650,565 cw(c9650,545) 9670,545 9670,320 cw(c9660,320) 9660,310 9420,310 cw(c9420,325) 9405,325 9405,555 cw(c9415,555) 9415,565
no net on Bottom Overlay "Bottom Layer-No Net" (solid): 9175,1045 9790,1045 cw(c9790,1025) 9810,1025 9810,905 cw(c9795,905) 9795,890 9145,890 cw(c9145,910) 9125,910 9125,1020 cw(c9150,1020) 9150,1045 9175,1045

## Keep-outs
Keep-Out Layer:
  lines w10: 0,0 11574.8,0 ; 2.51,2.51 2.51,266.88 ccw(c-202.73,482.26) 0,700 0,1062.99 11574.8,1062.99 ; 11575,0 11575,1062.99
  lines w40: 1140,140 1660,140 1875,355 ; 1393.18,563.18 1580,750 ; 1585,755 1850,755

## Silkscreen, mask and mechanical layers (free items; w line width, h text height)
Top Overlay:
  lines w20: 5335,55 5335,590 ; 5930,755 6350,755 ; 6460,130 6640,130 ; 6765,840 7185,840 ; 6990,135 6990,390 ; 7015,495 7015,655 ; 7065,775 7830,775 ; 7590,50 7590,650 ; 7980,100 7980,240 ; 8110,425 8110,539.76 ; 8190,45 8190,610 ; 8950,460 8950,190 8955,185 ; 9720,45 9720,145 ; 10095,445 10470,445
  text "MOSDESIGN" at 5900,935 h100
  text "L" at 65,900 h30
  text "J11" at 6830,865 h30
  text "J12" at 7455,795 h30
  text "J8" at 6180,775 h30
  text "N" at 70,700 h30
  text "J15" at 8010,460 h30
  text "J19" at 10400,390 h30
  text "J17" at 8845,345 h30
  text "G" at 160,305 h30
  text "J16" at 8095,265 h30
  text "J13" at 7495,185 h30
  text "J14" at 7890,155 h30
  text "MOS-14Wx4/14Wx3" at 10130,115 h60
  text "J18" at 9740,100 h30
  text "J10" at 6955,65 h30
  text "J9" at 6535,60 h30
  text "14Wx2/28Wx2-P1" at 10195,40 h60
Bottom Overlay:
  rectangle: 4725,865 4900,1025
